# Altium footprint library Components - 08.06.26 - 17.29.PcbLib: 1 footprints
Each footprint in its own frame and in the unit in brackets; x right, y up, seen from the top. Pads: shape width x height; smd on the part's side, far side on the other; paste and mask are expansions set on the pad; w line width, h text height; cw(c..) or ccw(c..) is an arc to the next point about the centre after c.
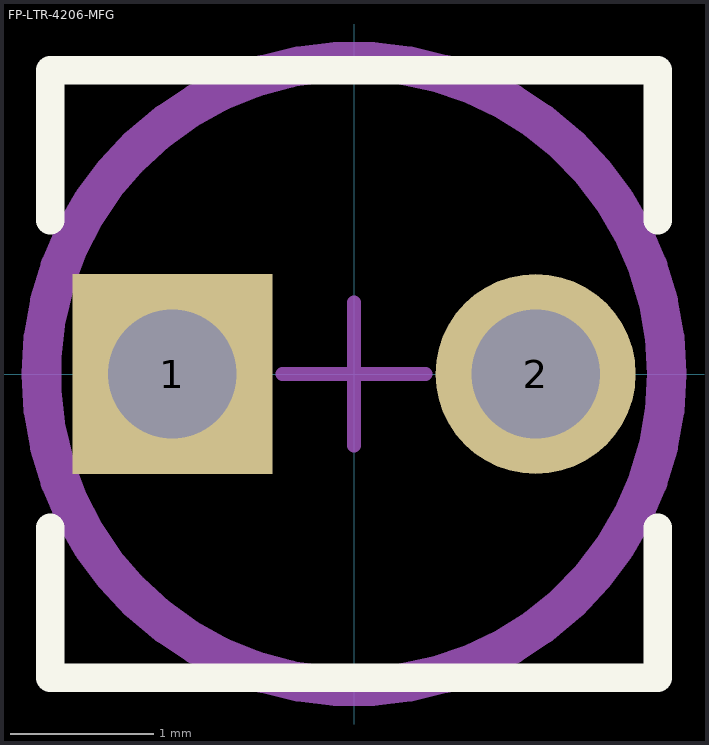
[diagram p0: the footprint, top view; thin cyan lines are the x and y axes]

## FP-LTR-4206-MFG [mm]
pads (2):
  rect 1.4x1.4 hole 0.9 paste-2539.97 mask+0: 1(-1.27,0)
  round 1.4 hole 0.9 paste-2539.97 mask+0: 2(1.27,0)
Top Overlay:
  lines w0.2: -2.125,-1.075 -2.125,-2.125 2.125,-2.125 2.125,-1.075 ; -2.125,1.075 -2.125,2.125 2.125,2.125 2.125,1.075
Top Assembly:
  text ".Designator" at 0,0.188 h1
Top 3D Body:
  circle w0.15: c0,0 r2.125
Top Courtyard:
  lines w0.2: -2.225,0 ccw(c0,0) 2.225,0 ccw(c0,0) -2.225,0
Top Component Center:
  lines w0.1: -0.5,0 0.5,0 ; 0,-0.5 0,0.5
3D body "Trans_Lite-On_LTR-4206_eec.STEP": height 0.25, standoff 0, extent -2.225,-2.225 2.225,2.225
